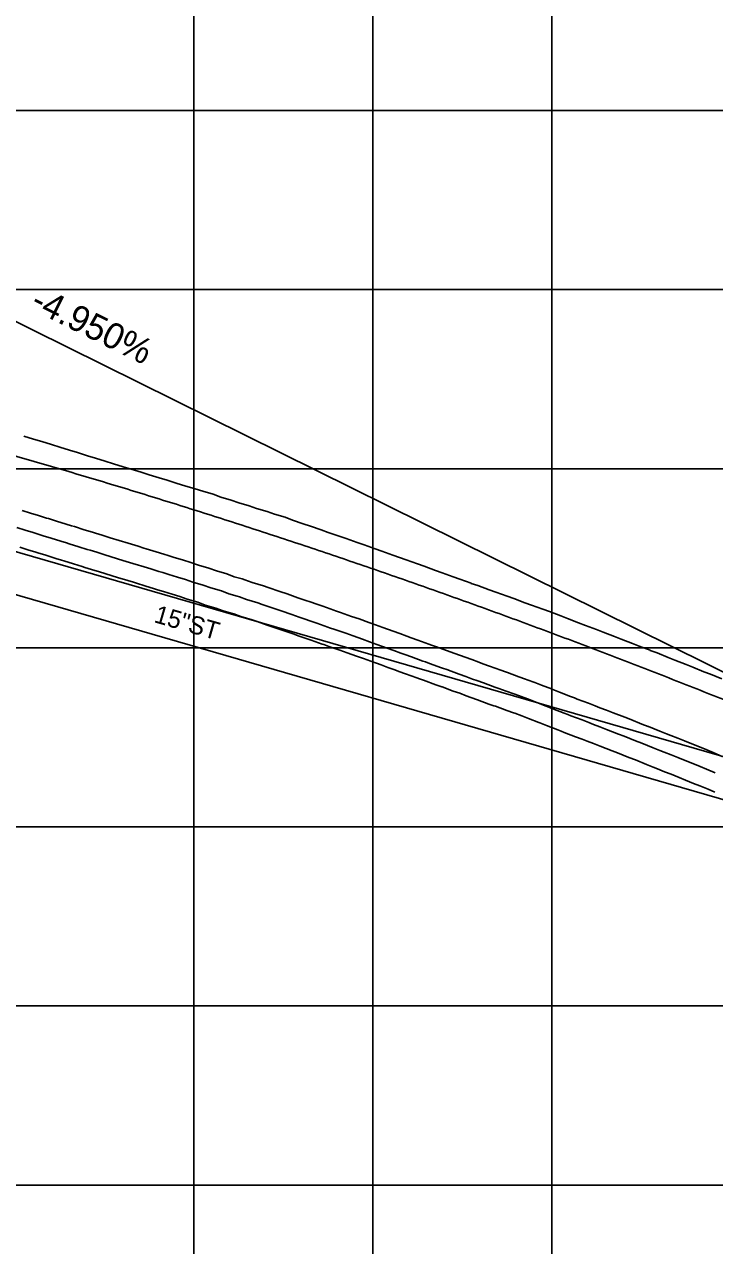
# Model space of a CAD drawing. Extents: x -7164 to 2214450, y -19642 to 253469.
# Drawn here: x 2302.7 to 2495.4, y -1766.9 to -1426 of the extents above; entities that cross this region are included whole.
import ezdxf

# ---------------------------------------------------------------- set-up
doc = ezdxf.new("R2010")
doc.units = 0
for name, color, linetype in [('DESIGN - PROFILE - Proposed', 7, 'Continuous'), ('DESIGN - PROFILE - Proposed Text', 7, 'Continuous'), ('DESIGN - SHEET - Light Grid', 7, 'Continuous'), ('SURVEY - PROFILE - Drainage - Storm Sewer', 7, 'Continuous'), ('SURVEY - PROFILE - Drainage - Storm Sewer Text', 7, 'Continuous'), ('SURVEY - PROFILE - Ground Line with Text', 7, 'Continuous'), ('SURVEY - PROFILE - Utilities - Cable with Text', 7, 'Continuous'), ('SURVEY - PROFILE - Utilities - Electric with Text', 7, 'Continuous'), ('XTREE', 7, 'Continuous')]:
    doc.layers.add(name, color=color, linetype=linetype)

msp = doc.modelspace()

# ---------------------------------------------------------------- linework, layer by layer
at = {"layer": 'DESIGN - PROFILE - Proposed'}
msp.add_spline([(1885.96, -1477.23), (1901.46, -1478.04), (1916.96, -1478.98), (1932.46, -1480.07), (1947.96, -1481.29), (1963.46, -1482.65), (1978.96, -1484.15), (1994.46, -1485.79), (2009.96, -1487.57), (2025.46, -1489.49), (2040.96, -1491.54), (2056.46, -1493.73), (2071.96, -1496.07), (2087.46, -1498.54), (2102.96, -1501.15), (2118.46, -1503.9), (2133.96, -1506.79), (2149.46, -1509.81), (2164.96, -1512.98), (2180.46, -1516.28), (2195.96, -1519.72), (2211.46, -1523.3), (2226.96, -1527.02), (2242.46, -1530.88), (2257.96, -1534.88), (2273.46, -1539.01), (2288.96, -1543.29), (2304.46, -1547.7), (2319.96, -1552.25), (2335.46, -1556.94), (2350.96, -1561.77), (2366.46, -1566.74), (2381.96, -1571.85), (2397.46, -1577.09), (2412.96, -1582.48), (2428.46, -1588), (2443.96, -1593.66), (2459.46, -1599.46), (2474.96, -1605.4), (2490.46, -1611.48), (2505.96, -1617.69), (2521.46, -1624.05), (2536.96, -1630.54), (2552.46, -1637.18), (2567.96, -1643.95), (2583.46, -1650.86), (2598.96, -1657.9), (2614.46, -1665.09), (2629.96, -1672.42), (2645.46, -1679.88), (2660.96, -1687.48)], degree=3, dxfattribs=at)
msp.add_spline([(1885.96, -1477.23), (1901.46, -1478.04), (1916.96, -1478.98), (1932.46, -1480.07), (1947.96, -1481.29), (1963.46, -1482.65), (1978.96, -1484.15), (1994.46, -1485.79), (2009.96, -1487.57), (2025.46, -1489.49), (2040.96, -1491.54), (2056.46, -1493.73), (2071.96, -1496.07), (2087.46, -1498.54), (2102.96, -1501.15), (2118.46, -1503.9), (2133.96, -1506.79), (2149.46, -1509.81), (2164.96, -1512.98), (2180.46, -1516.28), (2195.96, -1519.72), (2211.46, -1523.3), (2226.96, -1527.02), (2242.46, -1530.88), (2257.96, -1534.88), (2273.46, -1539.01), (2288.96, -1543.29), (2304.46, -1547.7), (2319.96, -1552.25), (2335.46, -1556.94), (2350.96, -1561.77), (2366.46, -1566.74), (2381.96, -1571.85), (2397.46, -1577.09), (2412.96, -1582.48), (2428.46, -1588), (2443.96, -1593.66), (2459.46, -1599.46), (2474.96, -1605.4), (2490.46, -1611.48), (2505.96, -1617.69), (2521.46, -1624.05), (2536.96, -1630.54), (2552.46, -1637.18), (2567.96, -1643.95), (2583.46, -1650.86), (2598.96, -1657.9), (2614.46, -1665.09), (2629.96, -1672.42), (2645.46, -1679.88), (2660.96, -1687.48)], degree=3, dxfattribs=at)
at = {"layer": 'DESIGN - PROFILE - Proposed Text'}
msp.add_line((2660.96, -1687.48), (2278.84, -1498.33), dxfattribs=at)
msp.add_line((2660.96, -1687.48), (2278.84, -1498.33), dxfattribs=at)
at = {"layer": 'DESIGN - SHEET - Light Grid'}
for p, q in [((2350, -3000), (2350, -1000)), ((2350, -3000), (2350, -1000)), ((2400, -3000), (2400, -1000)), ((2400, -3000), (2400, -1000)), ((2450, -3000), (2450, -1000)), ((2450, -3000), (2450, -1000)), ((0, -1450), (12400, -1450)), ((0, -1450), (12400, -1450)), ((0, -1500), (12400, -1500)), ((0, -1500), (12400, -1500)), ((0, -1550), (12400, -1550)), ((0, -1550), (12400, -1550)), ((0, -1600), (12400, -1600)), ((0, -1600), (12400, -1600)), ((0, -1650), (12400, -1650)), ((0, -1650), (12400, -1650)), ((0, -1700), (12400, -1700)), ((0, -1700), (12400, -1700)), ((0, -1750), (12400, -1750)), ((0, -1750), (12400, -1750))]:
    msp.add_line(p, q, dxfattribs=at)
at = {"layer": 'SURVEY - PROFILE - Drainage - Storm Sewer'}
for p, q in [((2102.49, -1515.9), (2548.32, -1645)), ((2102.49, -1515.9), (2548.32, -1645)), ((2102.49, -1527.9), (2548.32, -1657)), ((2102.49, -1527.9), (2548.32, -1657))]:
    msp.add_line(p, q, dxfattribs=at)
at = {"layer": 'SURVEY - PROFILE - Ground Line with Text'}
msp.add_lwpolyline([(2302.56, -1540.87), (2305.24, -1541.72), (2307.56, -1542.42), (2310.27, -1543.27), (2312.56, -1543.97), (2315.28, -1544.83), (2317.55, -1545.51), (2320.29, -1546.38), (2322.55, -1547.06), (2325.28, -1547.92), (2327.55, -1548.6), (2327.56, -1548.6), (2330.31, -1549.45), (2332.56, -1550.15), (2335.34, -1551), (2337.56, -1551.69), (2340.37, -1552.55), (2342.55, -1553.22), (2345.39, -1554.1), (2347.55, -1554.76), (2350.4, -1555.64), (2352.55, -1556.3), (2352.56, -1556.3), (2355.44, -1557.13), (2357.56, -1557.92), (2360.47, -1558.75), (2362.56, -1559.52), (2365.49, -1560.36), (2367.56, -1561.13), (2370.51, -1561.97), (2372.55, -1562.73), (2375.51, -1563.57), (2377.55, -1564.33), (2377.56, -1564.33), (2380.56, -1565.37), (2382.56, -1566.06), (2385.59, -1567.11), (2387.56, -1567.79), (2390.62, -1568.86), (2392.56, -1569.52), (2395.64, -1570.59), (2397.55, -1571.26), (2400.65, -1572.33), (2402.55, -1572.99), (2405.63, -1574.11), (2407.48, -1574.77), (2409.36, -1575.44), (2412.48, -1576.57), (2414.35, -1577.25), (2417.48, -1578.38), (2419.35, -1579.05), (2422.47, -1580.19), (2424.35, -1580.86), (2427.47, -1582), (2427.49, -1582.01), (2429.37, -1582.64), (2432.48, -1583.81), (2434.35, -1584.44), (2437.48, -1585.62), (2439.34, -1586.25), (2442.48, -1587.43), (2444.35, -1588.06), (2447.47, -1589.24), (2449.36, -1589.88), (2452.47, -1591.05), (2452.49, -1591.06), (2454.38, -1591.81), (2457.49, -1592.99), (2459.36, -1593.73), (2462.48, -1594.91), (2464.35, -1595.66), (2467.48, -1596.84), (2469.35, -1597.59), (2472.48, -1598.77), (2474.36, -1599.52), (2477.47, -1600.7), (2477.49, -1600.71), (2479.38, -1601.43), (2482.49, -1602.69), (2484.36, -1603.41), (2487.48, -1604.68), (2489.35, -1605.39), (2492.48, -1606.67), (2494.35, -1607.38), (2497.47, -1608.66)], dxfattribs=at)
msp.add_lwpolyline([(2302.56, -1540.87), (2305.24, -1541.72), (2307.56, -1542.42), (2310.27, -1543.27), (2312.56, -1543.97), (2315.28, -1544.83), (2317.55, -1545.51), (2320.29, -1546.38), (2322.55, -1547.06), (2325.28, -1547.92), (2327.55, -1548.6), (2327.56, -1548.6), (2330.31, -1549.45), (2332.56, -1550.15), (2335.34, -1551), (2337.56, -1551.69), (2340.37, -1552.55), (2342.55, -1553.22), (2345.39, -1554.1), (2347.55, -1554.76), (2350.4, -1555.64), (2352.55, -1556.3), (2352.56, -1556.3), (2355.44, -1557.13), (2357.56, -1557.92), (2360.47, -1558.75), (2362.56, -1559.52), (2365.49, -1560.36), (2367.56, -1561.13), (2370.51, -1561.97), (2372.55, -1562.73), (2375.51, -1563.57), (2377.55, -1564.33), (2377.56, -1564.33), (2380.56, -1565.37), (2382.56, -1566.06), (2385.59, -1567.11), (2387.56, -1567.79), (2390.62, -1568.86), (2392.56, -1569.52), (2395.64, -1570.59), (2397.55, -1571.26), (2400.65, -1572.33), (2402.55, -1572.99), (2405.63, -1574.11), (2407.48, -1574.77), (2409.36, -1575.44), (2412.48, -1576.57), (2414.35, -1577.25), (2417.48, -1578.38), (2419.35, -1579.05), (2422.47, -1580.19), (2424.35, -1580.86), (2427.47, -1582), (2427.49, -1582.01), (2429.37, -1582.64), (2432.48, -1583.81), (2434.35, -1584.44), (2437.48, -1585.62), (2439.34, -1586.25), (2442.48, -1587.43), (2444.35, -1588.06), (2447.47, -1589.24), (2449.36, -1589.88), (2452.47, -1591.05), (2452.49, -1591.06), (2454.38, -1591.81), (2457.49, -1592.99), (2459.36, -1593.73), (2462.48, -1594.91), (2464.35, -1595.66), (2467.48, -1596.84), (2469.35, -1597.59), (2472.48, -1598.77), (2474.36, -1599.52), (2477.47, -1600.7), (2477.49, -1600.71), (2479.38, -1601.43), (2482.49, -1602.69), (2484.36, -1603.41), (2487.48, -1604.68), (2489.35, -1605.39), (2492.48, -1606.67), (2494.35, -1607.38), (2497.47, -1608.66)], dxfattribs=at)
at = {"layer": 'SURVEY - PROFILE - Utilities - Cable with Text'}
msp.add_lwpolyline([(2301.42, -1571.94), (2303.71, -1572.63), (2305.86, -1573.31), (2306.44, -1573.49), (2308.71, -1574.18), (2311.45, -1575.04), (2313.02, -1575.52), (2313.72, -1575.73), (2316.45, -1576.59), (2318.82, -1577.3), (2319.59, -1577.54), (2321.47, -1578.12), (2323.72, -1578.81), (2328.73, -1580.36), (2331.55, -1581.22), (2333.13, -1581.71), (2333.74, -1581.9), (2336.58, -1582.77), (2338.74, -1583.44), (2339.92, -1583.8), (2341.59, -1584.31), (2344, -1585.05), (2346.09, -1585.66), (2348.2, -1586.44), (2351.11, -1587.28), (2353.21, -1588.05), (2356.15, -1588.89), (2358.22, -1589.66), (2360.79, -1590.39), (2361.17, -1590.5), (2363.12, -1591.23), (2366.35, -1592.17), (2367.43, -1592.57), (2370.78, -1593.73), (2372.78, -1594.42), (2375.8, -1595.47), (2377.76, -1596.14), (2379.46, -1596.73), (2380.81, -1597.2), (2382.75, -1597.87), (2385.83, -1598.94), (2386.31, -1599.11), (2387.73, -1599.6), (2390.8, -1600.67), (2392.82, -1601.37), (2395.48, -1602.33), (2397.38, -1603.01), (2399.43, -1603.75), (2402.3, -1604.79), (2404.17, -1605.46), (2406.13, -1606.17), (2407.29, -1606.6), (2409.15, -1607.26), (2412.29, -1608.4), (2413.01, -1608.66), (2414.14, -1609.07), (2417.57, -1610.32), (2419.29, -1610.9), (2419.35, -1610.92), (2422.41, -1612.07), (2424.27, -1612.7), (2426.1, -1613.39), (2427.39, -1613.88), (2429.25, -1614.5), (2432.39, -1615.69), (2433.84, -1616.18), (2434.25, -1616.31), (2437.39, -1617.5), (2439.26, -1618.13), (2439.63, -1618.27), (2441.65, -1619.03), (2443.51, -1619.77), (2446.35, -1620.85), (2446.63, -1620.95), (2448.49, -1621.69), (2451.63, -1622.88), (2452.63, -1623.28), (2453.48, -1623.62), (2456.62, -1624.81), (2458.48, -1625.55), (2459.88, -1626.08), (2461.61, -1626.73), (2463.48, -1627.48), (2466.83, -1628.75), (2468.36, -1629.33), (2471.48, -1630.6), (2473.33, -1631.31), (2473.34, -1631.31), (2476.47, -1632.59), (2478.33, -1633.3), (2479.47, -1633.76), (2481.47, -1634.58), (2483.32, -1635.29), (2489.58, -1637.84), (2491.33, -1638.5), (2493.61, -1639.46), (2495.5, -1640.32)], dxfattribs=at)
msp.add_lwpolyline([(2301.42, -1571.94), (2303.71, -1572.63), (2305.86, -1573.31), (2306.44, -1573.49), (2308.71, -1574.18), (2311.45, -1575.04), (2313.02, -1575.52), (2313.72, -1575.73), (2316.45, -1576.59), (2318.82, -1577.3), (2319.59, -1577.54), (2321.47, -1578.12), (2323.72, -1578.81), (2328.73, -1580.36), (2331.55, -1581.22), (2333.13, -1581.71), (2333.74, -1581.9), (2336.58, -1582.77), (2338.74, -1583.44), (2339.92, -1583.8), (2341.59, -1584.31), (2344, -1585.05), (2346.09, -1585.66), (2348.2, -1586.44), (2351.11, -1587.28), (2353.21, -1588.05), (2356.15, -1588.89), (2358.22, -1589.66), (2360.79, -1590.39), (2361.17, -1590.5), (2363.12, -1591.23), (2366.35, -1592.17), (2367.43, -1592.57), (2370.78, -1593.73), (2372.78, -1594.42), (2375.8, -1595.47), (2377.76, -1596.14), (2379.46, -1596.73), (2380.81, -1597.2), (2382.75, -1597.87), (2385.83, -1598.94), (2386.31, -1599.11), (2387.73, -1599.6), (2390.8, -1600.67), (2392.82, -1601.37), (2395.48, -1602.33), (2397.38, -1603.01), (2399.43, -1603.75), (2402.3, -1604.79), (2404.17, -1605.46), (2406.13, -1606.17), (2407.29, -1606.6), (2409.15, -1607.26), (2412.29, -1608.4), (2413.01, -1608.66), (2414.14, -1609.07), (2417.57, -1610.32), (2419.29, -1610.9), (2419.35, -1610.92), (2422.41, -1612.07), (2424.27, -1612.7), (2426.1, -1613.39), (2427.39, -1613.88), (2429.25, -1614.5), (2432.39, -1615.69), (2433.84, -1616.18), (2434.25, -1616.31), (2437.39, -1617.5), (2439.26, -1618.13), (2439.63, -1618.27), (2441.65, -1619.03), (2443.51, -1619.77), (2446.35, -1620.85), (2446.63, -1620.95), (2448.49, -1621.69), (2451.63, -1622.88), (2452.63, -1623.28), (2453.48, -1623.62), (2456.62, -1624.81), (2458.48, -1625.55), (2459.88, -1626.08), (2461.61, -1626.73), (2463.48, -1627.48), (2466.83, -1628.75), (2468.36, -1629.33), (2471.48, -1630.6), (2473.33, -1631.31), (2473.34, -1631.31), (2476.47, -1632.59), (2478.33, -1633.3), (2479.47, -1633.76), (2481.47, -1634.58), (2483.32, -1635.29), (2489.58, -1637.84), (2491.33, -1638.5), (2493.61, -1639.46), (2495.5, -1640.32)], dxfattribs=at)
at = {"layer": 'SURVEY - PROFILE - Utilities - Electric with Text'}
for points in [[(2302.1, -1561.67), (2304.37, -1562.39), (2306.66, -1563.08), (2308.87, -1563.78), (2309.39, -1563.94), (2311.66, -1564.62), (2314.39, -1565.49), (2315.9, -1565.94), (2316.67, -1566.17), (2319.4, -1567.03), (2321.74, -1567.74), (2322.54, -1567.98), (2324.42, -1568.56), (2326.67, -1569.26), (2331.67, -1570.8), (2334.49, -1571.67), (2336.08, -1572.16), (2336.68, -1572.34), (2339.52, -1573.21), (2341.68, -1573.88), (2342.86, -1574.24), (2344.53, -1574.75), (2346.86, -1575.47), (2349.23, -1576.15), (2351.32, -1576.93), (2354.23, -1577.77), (2356.33, -1578.54), (2359.27, -1579.38), (2361.33, -1580.15), (2363.54, -1580.78), (2364.28, -1580.99), (2366.27, -1581.73), (2369.5, -1582.67), (2370.81, -1583.16), (2374.04, -1584.28), (2376.04, -1584.97), (2379.07, -1586.02), (2381.03, -1586.69), (2382.75, -1587.29), (2384.09, -1587.75), (2386.02, -1588.42), (2389.1, -1589.49), (2389.57, -1589.66), (2391.01, -1590.15), (2394.08, -1591.22), (2396.16, -1591.94), (2398.86, -1592.93), (2400.75, -1593.6), (2402.83, -1594.34), (2405.7, -1595.39), (2407.56, -1596.05), (2409.55, -1596.78), (2410.69, -1597.19), (2412.55, -1597.86), (2415.68, -1599), (2416.39, -1599.25), (2417.55, -1599.67), (2420.88, -1600.88), (2422.65, -1601.48), (2422.87, -1601.56), (2425.77, -1602.65), (2427.63, -1603.28), (2429.62, -1604.03), (2430.76, -1604.46), (2432.61, -1605.08), (2435.76, -1606.27), (2437.04, -1606.7), (2437.61, -1606.89), (2440.75, -1608.08), (2442.62, -1608.71), (2443.15, -1608.91), (2445.27, -1609.71), (2447.13, -1610.45), (2449.89, -1611.49), (2450.25, -1611.63), (2452.11, -1612.37), (2455.25, -1613.56), (2456.33, -1613.99), (2457.1, -1614.3), (2460.24, -1615.48), (2462.1, -1616.23), (2463.42, -1616.72), (2465.23, -1617.41), (2467.11, -1618.16), (2470.39, -1619.4), (2472.03, -1620.03), (2475.15, -1621.3), (2476.9, -1621.97), (2477.01, -1622.01), (2480.14, -1623.29), (2482, -1623.99), (2483.25, -1624.5), (2485.14, -1625.27), (2487, -1625.98), (2493.25, -1628.53), (2495.05, -1629.22), (2497.61, -1630.3)], [(2302.1, -1561.67), (2304.37, -1562.39), (2306.66, -1563.08), (2308.87, -1563.78), (2309.39, -1563.94), (2311.66, -1564.62), (2314.39, -1565.49), (2315.9, -1565.94), (2316.67, -1566.17), (2319.4, -1567.03), (2321.74, -1567.74), (2322.54, -1567.98), (2324.42, -1568.56), (2326.67, -1569.26), (2331.67, -1570.8), (2334.49, -1571.67), (2336.08, -1572.16), (2336.68, -1572.34), (2339.52, -1573.21), (2341.68, -1573.88), (2342.86, -1574.24), (2344.53, -1574.75), (2346.86, -1575.47), (2349.23, -1576.15), (2351.32, -1576.93), (2354.23, -1577.77), (2356.33, -1578.54), (2359.27, -1579.38), (2361.33, -1580.15), (2363.54, -1580.78), (2364.28, -1580.99), (2366.27, -1581.73), (2369.5, -1582.67), (2370.81, -1583.16), (2374.04, -1584.28), (2376.04, -1584.97), (2379.07, -1586.02), (2381.03, -1586.69), (2382.75, -1587.29), (2384.09, -1587.75), (2386.02, -1588.42), (2389.1, -1589.49), (2389.57, -1589.66), (2391.01, -1590.15), (2394.08, -1591.22), (2396.16, -1591.94), (2398.86, -1592.93), (2400.75, -1593.6), (2402.83, -1594.34), (2405.7, -1595.39), (2407.56, -1596.05), (2409.55, -1596.78), (2410.69, -1597.19), (2412.55, -1597.86), (2415.68, -1599), (2416.39, -1599.25), (2417.55, -1599.67), (2420.88, -1600.88), (2422.65, -1601.48), (2422.87, -1601.56), (2425.77, -1602.65), (2427.63, -1603.28), (2429.62, -1604.03), (2430.76, -1604.46), (2432.61, -1605.08), (2435.76, -1606.27), (2437.04, -1606.7), (2437.61, -1606.89), (2440.75, -1608.08), (2442.62, -1608.71), (2443.15, -1608.91), (2445.27, -1609.71), (2447.13, -1610.45), (2449.89, -1611.49), (2450.25, -1611.63), (2452.11, -1612.37), (2455.25, -1613.56), (2456.33, -1613.99), (2457.1, -1614.3), (2460.24, -1615.48), (2462.1, -1616.23), (2463.42, -1616.72), (2465.23, -1617.41), (2467.11, -1618.16), (2470.39, -1619.4), (2472.03, -1620.03), (2475.15, -1621.3), (2476.9, -1621.97), (2477.01, -1622.01), (2480.14, -1623.29), (2482, -1623.99), (2483.25, -1624.5), (2485.14, -1625.27), (2487, -1625.98), (2493.25, -1628.53), (2495.05, -1629.22), (2497.61, -1630.3)], [(2300.59, -1566.44), (2302.89, -1567.16), (2305.18, -1567.85), (2307.37, -1568.54), (2307.92, -1568.72), (2310.19, -1569.4), (2312.92, -1570.26), (2314.46, -1570.73), (2315.19, -1570.95), (2317.92, -1571.81), (2320.28, -1572.52), (2321.06, -1572.76), (2322.95, -1573.34), (2325.19, -1574.04), (2330.2, -1575.58), (2333.02, -1576.45), (2334.6, -1576.93), (2335.21, -1577.12), (2338.05, -1577.99), (2340.21, -1578.66), (2341.39, -1579.02), (2343.06, -1579.53), (2345.43, -1580.26), (2347.66, -1580.91), (2349.76, -1581.69), (2352.67, -1582.52), (2354.77, -1583.3), (2357.71, -1584.14), (2359.77, -1584.9), (2362.16, -1585.59), (2362.73, -1585.75), (2364.69, -1586.48), (2367.92, -1587.42), (2369.12, -1587.87), (2372.41, -1589.01), (2374.41, -1589.69), (2377.43, -1590.74), (2379.4, -1591.42), (2381.1, -1592.01), (2382.45, -1592.48), (2384.38, -1593.14), (2387.47, -1594.22), (2387.94, -1594.38), (2389.37, -1594.87), (2392.44, -1595.95), (2394.49, -1596.66), (2397.17, -1597.63), (2399.06, -1598.31), (2401.13, -1599.05), (2404, -1600.09), (2405.87, -1600.76), (2407.84, -1601.48), (2408.99, -1601.89), (2410.85, -1602.56), (2413.98, -1603.7), (2414.7, -1603.96), (2415.84, -1604.37), (2419.22, -1605.6), (2420.97, -1606.19), (2421.11, -1606.24), (2424.09, -1607.36), (2425.95, -1607.99), (2427.86, -1608.71), (2429.08, -1609.17), (2430.93, -1609.79), (2434.07, -1610.98), (2435.44, -1611.44), (2435.93, -1611.6), (2439.07, -1612.79), (2440.94, -1613.42), (2441.39, -1613.59), (2443.46, -1614.37), (2445.32, -1615.11), (2448.12, -1616.17), (2448.44, -1616.29), (2450.3, -1617.03), (2453.44, -1618.22), (2454.48, -1618.64), (2455.29, -1618.96), (2458.43, -1620.15), (2460.29, -1620.89), (2461.65, -1621.4), (2463.42, -1622.07), (2465.3, -1622.82), (2468.61, -1624.07), (2470.2, -1624.68), (2473.32, -1625.95), (2475.11, -1626.64), (2475.17, -1626.66), (2478.31, -1627.94), (2480.16, -1628.65), (2481.36, -1629.13), (2483.3, -1629.92), (2485.16, -1630.63), (2491.42, -1633.18), (2493.19, -1633.86), (2495.61, -1634.88)], [(2300.59, -1566.44), (2302.89, -1567.16), (2305.18, -1567.85), (2307.37, -1568.54), (2307.92, -1568.72), (2310.19, -1569.4), (2312.92, -1570.26), (2314.46, -1570.73), (2315.19, -1570.95), (2317.92, -1571.81), (2320.28, -1572.52), (2321.06, -1572.76), (2322.95, -1573.34), (2325.19, -1574.04), (2330.2, -1575.58), (2333.02, -1576.45), (2334.6, -1576.93), (2335.21, -1577.12), (2338.05, -1577.99), (2340.21, -1578.66), (2341.39, -1579.02), (2343.06, -1579.53), (2345.43, -1580.26), (2347.66, -1580.91), (2349.76, -1581.69), (2352.67, -1582.52), (2354.77, -1583.3), (2357.71, -1584.14), (2359.77, -1584.9), (2362.16, -1585.59), (2362.73, -1585.75), (2364.69, -1586.48), (2367.92, -1587.42), (2369.12, -1587.87), (2372.41, -1589.01), (2374.41, -1589.69), (2377.43, -1590.74), (2379.4, -1591.42), (2381.1, -1592.01), (2382.45, -1592.48), (2384.38, -1593.14), (2387.47, -1594.22), (2387.94, -1594.38), (2389.37, -1594.87), (2392.44, -1595.95), (2394.49, -1596.66), (2397.17, -1597.63), (2399.06, -1598.31), (2401.13, -1599.05), (2404, -1600.09), (2405.87, -1600.76), (2407.84, -1601.48), (2408.99, -1601.89), (2410.85, -1602.56), (2413.98, -1603.7), (2414.7, -1603.96), (2415.84, -1604.37), (2419.22, -1605.6), (2420.97, -1606.19), (2421.11, -1606.24), (2424.09, -1607.36), (2425.95, -1607.99), (2427.86, -1608.71), (2429.08, -1609.17), (2430.93, -1609.79), (2434.07, -1610.98), (2435.44, -1611.44), (2435.93, -1611.6), (2439.07, -1612.79), (2440.94, -1613.42), (2441.39, -1613.59), (2443.46, -1614.37), (2445.32, -1615.11), (2448.12, -1616.17), (2448.44, -1616.29), (2450.3, -1617.03), (2453.44, -1618.22), (2454.48, -1618.64), (2455.29, -1618.96), (2458.43, -1620.15), (2460.29, -1620.89), (2461.65, -1621.4), (2463.42, -1622.07), (2465.3, -1622.82), (2468.61, -1624.07), (2470.2, -1624.68), (2473.32, -1625.95), (2475.11, -1626.64), (2475.17, -1626.66), (2478.31, -1627.94), (2480.16, -1628.65), (2481.36, -1629.13), (2483.3, -1629.92), (2485.16, -1630.63), (2491.42, -1633.18), (2493.19, -1633.86), (2495.61, -1634.88)]]:
    msp.add_lwpolyline(points, dxfattribs=at)
at = {"layer": 'XTREE'}
msp.add_line((2273.46, -1495.67), (3810, -2256.26), dxfattribs=at)
msp.add_line((2273.46, -1495.67), (3810, -2256.26), dxfattribs=at)

# ---------------------------------------------------------------- texts
at = {"layer": 'DESIGN - PROFILE - Proposed Text'}
msp.add_text('-4.950%', height=7.2, rotation=333.6646, dxfattribs=at).set_placement((2303.99, -1505.2))
msp.add_text('-4.950%', height=7.2, rotation=333.6646, dxfattribs=at).set_placement((2303.99, -1505.2))
at = {"layer": 'SURVEY - PROFILE - Drainage - Storm Sewer Text'}
msp.add_text('15"ST', height=5, rotation=343.9148, dxfattribs=at).set_placement((2338.65, -1592.8))
msp.add_text('15"ST', height=5, rotation=343.9148, dxfattribs=at).set_placement((2338.65, -1592.8))

doc.saveas('drawing.dxf')
